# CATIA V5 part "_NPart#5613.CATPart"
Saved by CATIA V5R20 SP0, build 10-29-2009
Part number: DIN6325 Ø4X15_Parallel Pin ISO 8734 - 4 x 16 - A - St
Revision: ANY
Definition: UNKNOWN
Nomenclature: DIN6325 Ø4X15_Parallel Pin ISO 8734 - 4 x 16 - A - St
Source: Unknown
Bounding box of the stored display mesh (mm): x 0 to 16, y -2 to 2, z -2 to 2
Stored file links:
  C:\Users\Utente\Desktop\IO LAVORO\3D X SITO CF\CUMSA\3D files PR.233230\PR 263230\_NPart#5613.CATPart
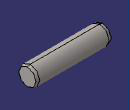
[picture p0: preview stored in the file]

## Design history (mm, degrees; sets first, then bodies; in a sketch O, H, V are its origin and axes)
Body1 "Base-Revolve" (main body)
  Solid1: solid without history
